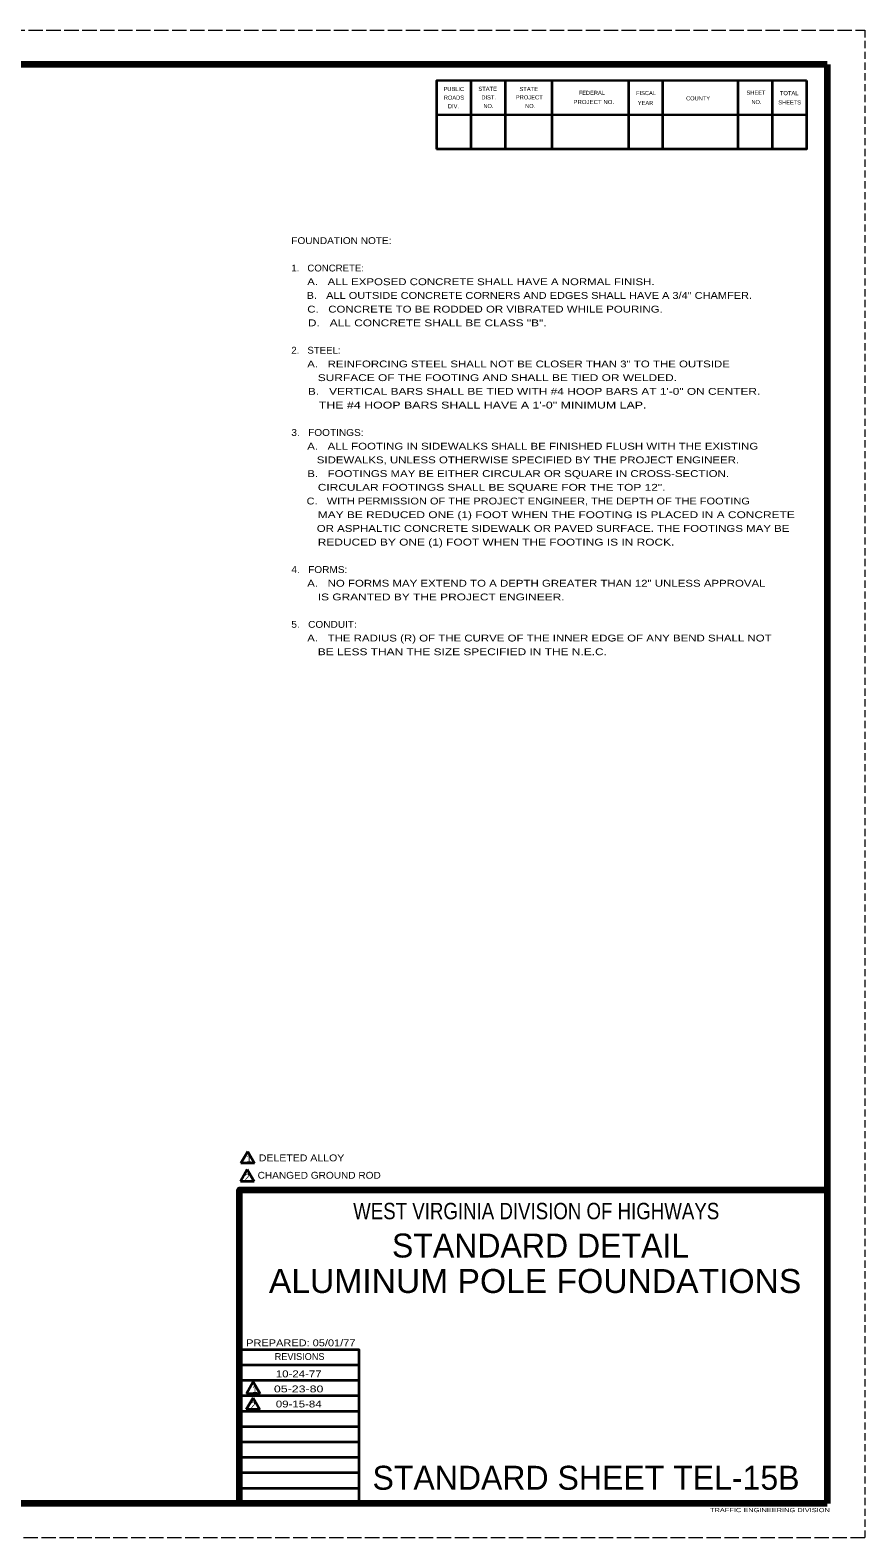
# Model space of a CAD drawing. Extents: x -1 to 679, y 0 to 440.
# Drawn here: x 435.3 to 679.1, y 0.3 to 440.3 of the extents above; entities that cross this region are included whole.
import ezdxf
from ezdxf.enums import TextEntityAlignment as Align

# ---------------------------------------------------------------- set-up
doc = ezdxf.new("R2010")
doc.units = 0
doc.header["$LTSCALE"] = 0.7
doc.linetypes.add('LONG_DASHED', pattern=[7.5, 6, -1.5])
doc.linetypes.add('MEDIUM_DASHED', pattern=[4.5, 3, -1.5])
doc.layers.add('1', color=7, linetype='Continuous', lineweight=53)
doc.layers.add('61', color=7, linetype='Continuous', lineweight=35)

msp = doc.modelspace()

# ---------------------------------------------------------------- linework, layer by layer
at = {"layer": '1', "linetype": 'MEDIUM_DASHED', "lineweight": 13}
msp.add_line((679.0735, 440.3012), (679.0535, 0.2812), dxfattribs=at)
at = {"layer": '1', "lineweight": 35}
for p, q in [((498.8678, 113.0383), (496.8678, 109.5742)), ((498.8678, 113.0383), (500.8678, 109.5742)), ((498.7067, 107.7227), (496.7067, 104.2586)), ((500.8678, 109.5742), (496.8678, 109.5742)), ((498.7067, 107.7227), (500.7067, 104.2586)), ((500.7067, 104.2586), (496.7067, 104.2586)), ((531.4535, 50.7012), (496.4735, 50.7012)), ((531.4535, 46.2012), (496.4735, 46.2012)), ((500.4781, 45.7526), (498.4781, 42.2885)), ((500.4781, 45.7526), (502.4781, 42.2885)), ((531.4535, 41.7012), (496.4735, 41.7012)), ((500.4317, 41.1732), (498.4317, 37.7091)), ((502.4781, 42.2885), (498.4781, 42.2885)), ((500.4317, 41.1732), (502.4317, 37.7091)), ((531.4535, 37.1812), (496.4735, 37.1812)), ((502.4317, 37.7091), (498.4317, 37.7091)), ((531.4535, 32.7012), (496.4735, 32.7012)), ((531.4535, 28.2212), (496.4735, 28.2212)), ((531.4535, 23.7212), (496.4735, 23.7212)), ((531.4535, 19.2212), (496.4735, 19.2212)), ((531.4535, 14.7012), (496.4735, 14.7012))]:
    msp.add_line(p, q, dxfattribs=at)
at = {"layer": '1', "lineweight": 158}
msp.add_lwpolyline([(496.4535, 10.2612), (496.4535, 101.8412), (668.1135, 101.8412)], dxfattribs=at)
at = {"layer": '1', "lineweight": 35}
msp.add_lwpolyline([(531.4535, 10.2212), (531.4535, 55.1812), (496.4735, 55.1812)], dxfattribs=at)
at = {"layer": '61', "linetype": 'LONG_DASHED', "lineweight": 13}
for p, q in [((-0.9465, 440.3012), (679.0735, 440.3012)), ((679.0535, 0.2812), (-1.0065, 0.2612))]:
    msp.add_line(p, q, dxfattribs=at)
at = {"layer": '61', "lineweight": 158}
for p, q in [((668.0935, 430.3012), (668.1135, 10.2612)), ((668.1135, 10.2612), (29.0535, 10.2812))]:
    msp.add_line(p, q, dxfattribs=at)
at = {"layer": '61'}
for p, q in [((564.0135, 425.5412), (564.0135, 405.5412)), ((574.0135, 425.5412), (574.0135, 405.5412)), ((587.6935, 425.5412), (587.6935, 405.5412)), ((610.0135, 425.5412), (610.0135, 405.5412)), ((620.0135, 425.5412), (620.0135, 405.5412)), ((641.9935, 425.5612), (641.9935, 405.5612)), ((651.9935, 425.5612), (651.9935, 405.5612)), ((662.0135, 415.5212), (553.9935, 415.5412))]:
    msp.add_line(p, q, dxfattribs=at)
at = {"layer": '61', "lineweight": 158}
msp.add_lwpolyline([(668.0935, 430.3012), (29.0535, 430.3012), (29.0535, 10.2812)], dxfattribs=at)
at = {"layer": '61'}
for points in [[(661.9935, 425.5612), (554.0135, 425.5412), (554.0135, 405.5412)], [(661.9935, 425.5612), (661.9935, 405.5612), (554.0135, 405.5412)]]:
    msp.add_lwpolyline(points, dxfattribs=at)

# ---------------------------------------------------------------- texts
at = {"layer": '1'}
for s, height, width, p in [('FOUNDATION NOTE:', 2, 1.1, (511.5983, 377.8727)), ('1.   CONCRETE:', 2, 1.05, (511.5983, 369.8727)), ('     A.   ALL EXPOSED CONCRETE SHALL HAVE A NORMAL FINISH.', 2, 1.25, (511.5983, 365.8727)), ('     B.   ALL OUTSIDE CONCRETE CORNERS AND EDGES SHALL HAVE A 3/4" CHAMFER.', 2, 1.2, (511.5983, 361.8727)), ('     C.   CONCRETE TO BE RODDED OR VIBRATED WHILE POURING.', 2, 1.25, (511.5983, 357.8727)), ('     D.   ALL CONCRETE SHALL BE CLASS "B".', 2, 1.3, (511.5983, 353.8727)), ('2.   STEEL:', 2, 1.05, (511.5983, 345.8727)), ('     A.   REINFORCING STEEL SHALL NOT BE CLOSER THAN 3" TO THE OUTSIDE', 2, 1.25, (511.5983, 341.8727)), ('        SURFACE OF THE FOOTING AND SHALL BE TIED OR WELDED.', 2, 1.3, (511.5983, 337.8727)), ('     B.   VERTICAL BARS SHALL BE TIED WITH #4 HOOP BARS AT 1\'-0" ON CENTER.', 2, 1.3, (511.5983, 333.8727)), ('        THE #4 HOOP BARS SHALL HAVE A 1\'-0" MINIMUM LAP.', 2, 1.35, (511.5983, 329.8727)), ('3.   FOOTINGS:', 2, 1.1, (511.5983, 321.8727)), ('     A.   ALL FOOTING IN SIDEWALKS SHALL BE FINISHED FLUSH WITH THE EXISTING', 2, 1.25, (511.5983, 317.8727)), ('        SIDEWALKS, UNLESS OTHERWISE SPECIFIED BY THE PROJECT ENGINEER.', 2, 1.25, (511.5983, 313.8727)), ('     B.   FOOTINGS MAY BE EITHER CIRCULAR OR SQUARE IN CROSS-SECTION.', 2, 1.25, (511.5983, 309.8727)), ('     C.   WITH PERMISSION OF THE PROJECT ENGINEER, THE DEPTH OF THE FOOTING', 2, 1.2, (511.5983, 301.8727)), ('        CIRCULAR FOOTINGS SHALL BE SQUARE FOR THE TOP 12".', 2, 1.3, (511.5983, 305.8727)), ('        MAY BE REDUCED ONE (1) FOOT WHEN THE FOOTING IS PLACED IN A CONCRETE', 2, 1.3, (511.5983, 297.8727)), ('        OR ASPHALTIC CONCRETE SIDEWALK OR PAVED SURFACE. THE FOOTINGS MAY BE', 2, 1.25, (511.5983, 293.8727)), ('        REDUCED BY ONE (1) FOOT WHEN THE FOOTING IS IN ROCK.', 2, 1.3, (511.5983, 289.8727)), ('4.   FORMS:', 2, 1.1, (511.5983, 281.8727)), ('     A.   NO FORMS MAY EXTEND TO A DEPTH GREATER THAN 12" UNLESS APPROVAL', 2, 1.25, (511.5983, 277.8727)), ('        IS GRANTED BY THE PROJECT ENGINEER.', 2, 1.3, (511.5983, 273.8727)), ('5.   CONDUIT:', 2, 1.1, (511.5983, 265.8727)), ('     A.   THE RADIUS (R) OF THE CURVE OF THE INNER EDGE OF ANY BEND SHALL NOT', 2, 1.25, (511.5983, 261.8727)), ('        BE LESS THAN THE SIZE SPECIFIED IN THE N.E.C.', 2, 1.3, (511.5983, 257.8727)), ('DELETED ALLOY', 2, 1.15, (502.1019, 110.1614)), ('2', 2, 0.9, (497.9931, 104.523)), ('CHANGED GROUND ROD', 2, 1.1, (501.7543, 105.0844)), ('PREPARED: 05/01/77', 1.998, 1.2, (498.4135, 56.1812)), ('2', 2, 0.9, (499.7664, 37.9849)), ('TRAFFIC ENGINEERING DIVISION', 1.2, 1.35, (633.8335, 7.7612))]:
    msp.add_text(s, height=height, dxfattribs=dict(at, width=width)).set_placement(p)
for s, height, p in [('1', 2, (498.4762, 109.9557)), ('REVISIONS', 1.998, (506.7335, 52.1812)), ('1', 2, (500.1811, 42.617)), ('STANDARD SHEET TEL-15B', 6.993, (535.2935, 14.3012))]:
    msp.add_text(s, height=height, dxfattribs=at).set_placement(p)
for s, height, width, p in [('WEST VIRGINIA DIVISION OF HIGHWAYS', 4.795, 0.85, (583.1018, 93.2412)), ('ALUMINUM POLE FOUNDATIONS', 6.993, 1.05, (582.779, 71.7274)), ('10-24-77', 2, 1.25, (513.7535, 47.1212)), ('05-23-80', 2, 1.35, (513.7335, 42.7212)), ('09-15-84', 2, 1.25, (513.7535, 38.3212))]:
    msp.add_text(s, height=height, dxfattribs=dict(at, width=width)).set_placement(p, align=Align.CENTER)
msp.add_text('STANDARD DETAIL', height=6.993, dxfattribs=at).set_placement((584.3705, 82.0812), align=Align.CENTER)
at = {"layer": '61'}
for s, rotation, p in [('PUBLIC', 0.033, (556.0535, 422.5212)), ('FEDERAL', 0.007, (595.5135, 421.4012)), ('FISCAL', 359.942, (612.2535, 421.3412)), ('SHEET', 0.059, (644.5135, 421.4612)), ('ROADS', 0.124, (556.1335, 420.0012)), ('DIV.', 359.932, (557.3335, 417.5012)), ('DIST.', 0.056, (567.0935, 420.0812)), ('YEAR', 0.105, (612.7735, 418.4412)), ('COUNTY', 0.069, (626.8735, 419.8012)), ('SHEETS', 359.959, (653.7935, 418.6212))]:
    msp.add_text(s, height=1.201, rotation=rotation, dxfattribs=at).set_placement(p)
for s, rotation, width, p in [('STATE', 0.059, 1.05, (566.2135, 422.5812)), ('STATE', 0.059, 1.05, (578.2135, 422.5212)), ('TOTAL', 359.926, 1.05, (654.2535, 421.3212)), ('NO.', 359.852, 0.95, (567.6735, 417.5612)), ('PROJECT', 359.908, 1.05, (577.1335, 420.1012)), ('NO.', 0.225, 0.95, (579.8735, 417.5612)), ('PROJECT NO.', 359.922, 1.1, (593.9735, 418.7412)), ('NO.', 359.852, 0.95, (645.9335, 418.7412))]:
    msp.add_text(s, height=1.201, rotation=rotation, dxfattribs=dict(at, width=width)).set_placement(p)

doc.saveas('drawing.dxf')
